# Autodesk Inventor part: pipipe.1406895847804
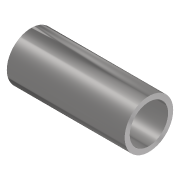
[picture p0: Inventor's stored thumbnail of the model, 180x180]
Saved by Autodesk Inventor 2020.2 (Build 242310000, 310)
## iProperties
Manager: www.cadconsulting.pl
Company: Fabian Stasiak CAD Consulting
IsCustomPart: 1
NAME: PIPING: JIS G 3458 Pipe
DATA: <meta><inlinegroups number="1" deflen="10"></inlinegroups><connections number="2"></connections><angles><a>3.14159265358979</a></angles></meta>
Created: 2014-08
Material: Stal, stopowa
Description: Rura
Document SubType Name: Modeling
Standard: JIS G 3458
Designer: F.Stasiak
Standards Organization: JIS
Language: pl-PL
Size Designation: 40 A x Sch 80 - 100
Categories: <MemberInstance><Categories><Category DisplayName="Rury cienko- i grubościenne" InternalName="4347fa0f-2144-441d-94cd-e3e15c92b736" Mnemonic="TUBEANDPIPE"><Cate
Stock Number: JIS G 3458 Rura 40 A x Sch 80
Density: 7.73 g/cm^3
Appearance: Częściowo polerowana
Catalog Web Link: www.expertbooks.pl
L: 118,000 mm
PL: 118,000 mm
Author: F.Stasiak
Subject: Zbiór ćwiczeń. Autodesk Inventor 2020. Kurs Professional
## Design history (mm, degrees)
sketch "Sketch1"
  geometry: C1 r 24.3 at (0, 0); C2 r 19.2 at (0, 0); 1 further point
  constraints: 2 centre point, 2 coincident, 1 concentric
  dimensions: "d0" = 48.6 diameter of C1 (= OD); "d1" = 38.4 diameter of C2 (= OD - 2 x t)
extrude "Extrusion1" new body sketch "Sketch1" distance "d2" = 118 (= L); taper "d3" = 0 deg
workaxis "Work Axis1"
workpoint "Work Point1"
workaxis "Work Axis2"
workpoint "Work Point2"
body "Solid1"
other parameters: "OD" = 48.6 [user parameter; used in 2 equation terms], "t" = 5.1 [user parameter; used in 1 equation term], "L" = 118 (= PL) [user parameter; used in 1 equation term], "ID" = 38.4 [user parameter], "PL" = 118 [user parameter; used in 1 equation term], "Size_Designation" = 12.345 [user parameter]
